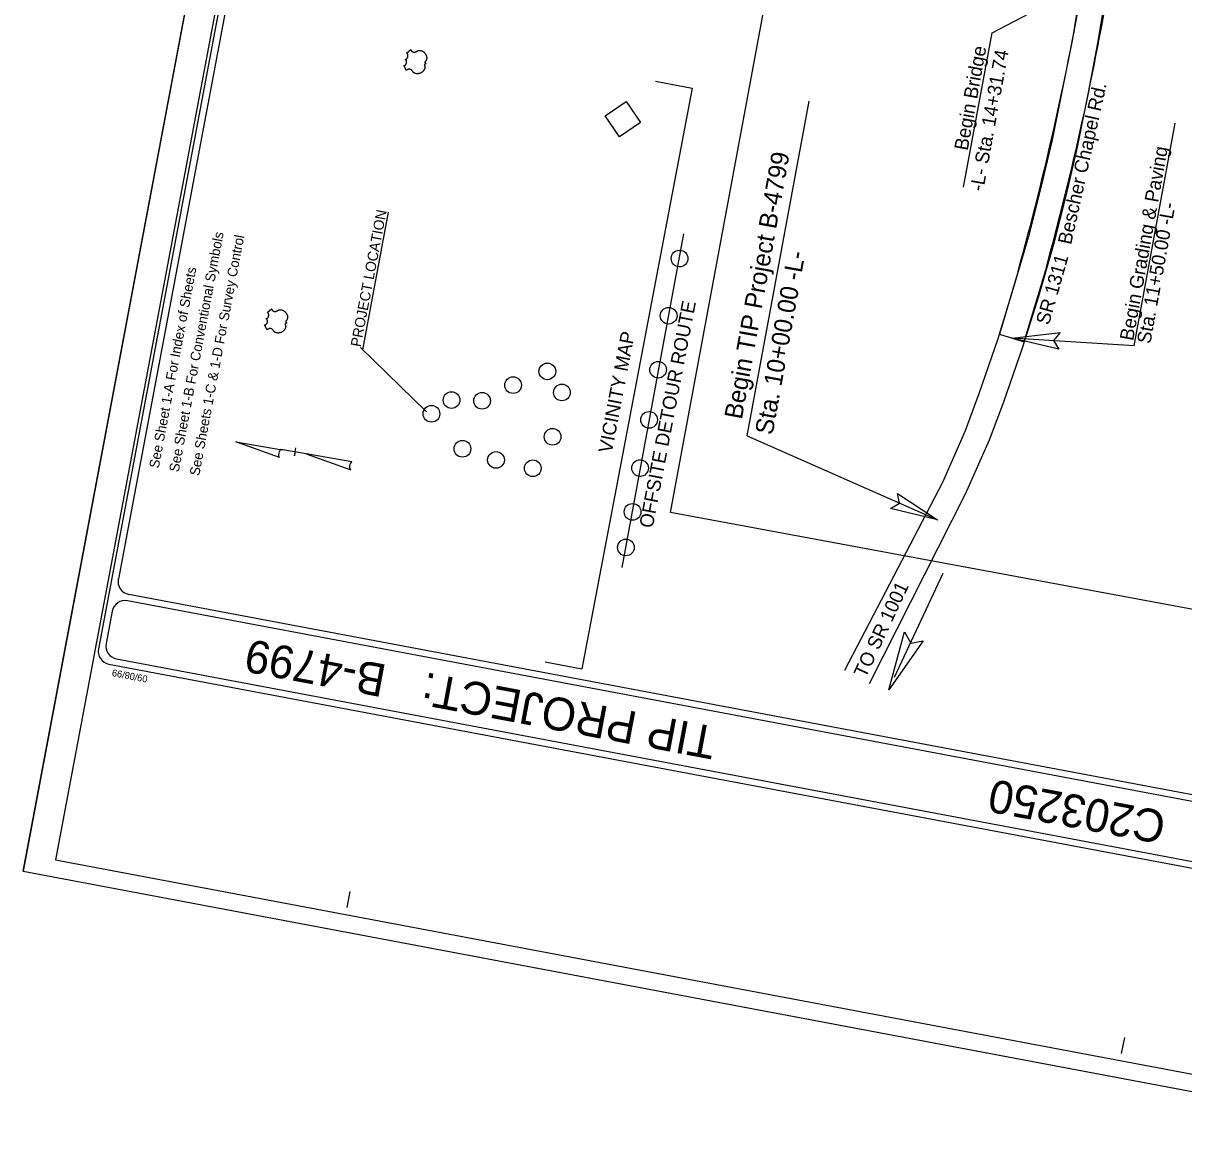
# Model space of a CAD drawing. Extents: x 1665923 to 1668724, y 690926 to 694920.
# Drawn here: x 1665923 to 1666806, y 691127 to 691976 of the extents above; entities that cross this region are included whole.
import ezdxf

# ---------------------------------------------------------------- set-up
doc = ezdxf.new("R2010")
doc.units = 0
for name, color, linetype in [('Default', 7, 'Continuous'), ('Prop Dimension Text', 7, 'Continuous'), ('Prop EOT', 7, 'Continuous'), ('Prop Horizontal Alignment Curve and Spiral Data', 7, 'Continuous'), ('Prop North Arrow for Plan Sheets CELL', 7, 'Continuous'), ('Prop Shade Light', 7, 'Continuous'), ('Prop Terminator CELL', 7, 'Continuous'), ('Sheet Cutting Line CELL', 7, 'Continuous'), ('Sheet Plot Border Inside CELL', 7, 'Continuous'), ('Sheet Plot Border Outside CELL', 7, 'Continuous'), ('Sheet Title CELL', 7, 'Continuous')]:
    doc.layers.add(name, color=color, linetype=linetype)

msp = doc.modelspace()

# ---------------------------------------------------------------- linework, layer by layer
at = {"layer": 'Default'}
for p, q in [((1666415.46, 691603.54), (1666618.88, 692699.33)), ((1666404.03, 691931.75), (1666432.05, 691926.47)), ((1666432.05, 691926.47), (1666348.03, 691484.55)), ((1666181.33, 691727.24), (1666200.8, 691832.11)), ((1666378.61, 691561.73), (1666425.72, 691815.52)), ((1666179.55, 691729.13), (1666229.73, 691680.15)), ((1666816.29, 691529.13), (1666415.46, 691603.54)), ((1666320.02, 691489.84), (1666348.03, 691484.55))]:
    msp.add_line(p, q, dxfattribs=at)
for points in [[(1666732.26, 692049.55), (1666730.91, 692032.26), (1666728.79, 692009.64), (1666721.43, 691963.98), (1666714.02, 691926.14), (1666705.99, 691887.06), (1666697.47, 691850.95), (1666687.93, 691813.6), (1666676.04, 691773.22), (1666664.76, 691735.72), (1666650.35, 691694.65), (1666639.71, 691665.8), (1666622.52, 691626.38), (1666547.97, 691483.33)], [(1666755.68, 692046.05), (1666754.42, 692038.11), (1666751.48, 692027.16), (1666748.07, 692006.66), (1666740.59, 691960.63), (1666733.56, 691923.1), (1666725.06, 691881.58), (1666717.07, 691846.51), (1666706.93, 691807.61), (1666695.59, 691767.97), (1666683.55, 691729.45), (1666669.04, 691687.44), (1666658.04, 691658.5), (1666640.09, 691618.11), (1666566.69, 691473.24)]]:
    msp.add_lwpolyline(points, dxfattribs=at)
for points in [[(1666212.42, 691943.67), (1666212.56, 691943.65), (1666212.73, 691943.65), (1666212.82, 691943.66), (1666213, 691943.7), (1666213.21, 691943.79), (1666213.44, 691943.92), (1666213.64, 691944.09), (1666213.75, 691944.2), (1666213.92, 691944.41), (1666214.08, 691944.64), (1666214.23, 691944.91), (1666214.35, 691945.19), (1666214.45, 691945.5), (1666214.52, 691945.82), (1666214.56, 691946.17), (1666214.57, 691946.56), (1666214.56, 691946.74), (1666214.53, 691946.95), (1666214.5, 691947.15), (1666214.43, 691947.37), (1666214.36, 691947.55), (1666214.3, 691947.69), (1666214.17, 691947.9), (1666214.02, 691948.08), (1666213.93, 691948.16), (1666213.85, 691948.23), (1666213.66, 691948.34), (1666213.58, 691948.38), (1666213.4, 691948.43), (1666213.56, 691948.41), (1666213.65, 691948.4), (1666213.75, 691948.41), (1666213.86, 691948.43), (1666214.02, 691948.47), (1666214.15, 691948.52), (1666214.36, 691948.64), (1666214.46, 691948.71), (1666214.55, 691948.78), (1666214.75, 691948.97), (1666214.94, 691949.21), (1666215.02, 691949.33), (1666215.1, 691949.45), (1666215.18, 691949.61), (1666215.26, 691949.78), (1666215.33, 691949.94), (1666215.39, 691950.12), (1666215.44, 691950.29), (1666215.47, 691950.44), (1666215.51, 691950.62), (1666215.54, 691950.79), (1666215.55, 691950.96), (1666215.56, 691951.16), (1666215.56, 691951.32), (1666215.54, 691951.53), (1666215.52, 691951.72), (1666215.48, 691951.9), (1666215.42, 691952.12), (1666215.35, 691952.31), (1666215.27, 691952.46), (1666215.17, 691952.63), (1666215.04, 691952.8), (1666214.94, 691952.9), (1666214.83, 691952.98), (1666214.72, 691953.06), (1666214.59, 691953.12), (1666214.48, 691953.16), (1666214.38, 691953.19), (1666217.72, 691955.96), (1666217.73, 691955.88), (1666217.78, 691955.68), (1666217.83, 691955.52), (1666217.95, 691955.26), (1666218.02, 691955.14), (1666218.09, 691955.02), (1666218.17, 691954.91), (1666218.24, 691954.81), (1666218.36, 691954.69), (1666218.47, 691954.58), (1666218.6, 691954.46), (1666218.72, 691954.37), (1666218.96, 691954.22), (1666219.12, 691954.13), (1666219.26, 691954.07), (1666219.55, 691953.97), (1666219.69, 691953.93), (1666219.83, 691953.9), (1666219.98, 691953.88), (1666220.12, 691953.86), (1666220.27, 691953.86), (1666220.41, 691953.86), (1666220.58, 691953.86), (1666220.77, 691953.89), (1666220.97, 691953.92), (1666221.29, 691954.01), (1666221.62, 691954.15), (1666221.82, 691954.25), (1666221.99, 691954.36), (1666222.2, 691954.53), (1666222.32, 691954.62), (1666222.48, 691954.72), (1666222.76, 691954.88), (1666222.89, 691954.94), (1666223.04, 691955), (1666223.19, 691955.05), (1666223.34, 691955.1), (1666223.48, 691955.14), (1666223.79, 691955.2), (1666224.08, 691955.22), (1666224.24, 691955.23), (1666224.58, 691955.23), (1666224.74, 691955.22), (1666225.07, 691955.18), (1666225.45, 691955.1), (1666225.81, 691954.99), (1666226.22, 691954.84), (1666226.47, 691954.73), (1666226.74, 691954.58), (1666226.98, 691954.44), (1666227.33, 691954.21), (1666227.58, 691954.02), (1666227.86, 691953.78), (1666228.03, 691953.62), (1666228.21, 691953.43), (1666228.42, 691953.21), (1666228.63, 691952.95), (1666228.85, 691952.65), (1666229.01, 691952.41), (1666229.18, 691952.11), (1666229.28, 691951.92), (1666229.4, 691951.66), (1666229.55, 691951.31), (1666229.66, 691950.98), (1666229.74, 691950.69), (1666229.79, 691950.44), (1666229.84, 691950.13), (1666229.87, 691949.61), (1666229.87, 691949.42), (1666229.86, 691949.2), (1666229.84, 691949), (1666229.81, 691948.81), (1666229.76, 691948.55), (1666229.68, 691948.29), (1666229.6, 691948.06), (1666229.49, 691947.81), (1666229.36, 691947.57), (1666229.22, 691947.34), (1666229.05, 691947.13), (1666228.7, 691946.77), (1666228.61, 691946.66), (1666228.58, 691946.6), (1666228.54, 691946.44), (1666228.54, 691946.29), (1666228.57, 691946.12), (1666228.6, 691946.02), (1666228.66, 691945.88), (1666228.71, 691945.77), (1666228.8, 691945.63), (1666228.87, 691945.54), (1666228.93, 691945.46), (1666229.09, 691945.31), (1666229.16, 691945.25), (1666229.27, 691945.18), (1666229.42, 691945.11), (1666229.21, 691945.1), (1666229.06, 691945.07), (1666228.92, 691945.02), (1666228.8, 691944.97), (1666228.65, 691944.88), (1666228.52, 691944.8), (1666228.4, 691944.69), (1666228.29, 691944.58), (1666228.21, 691944.48), (1666228.15, 691944.39), (1666228.1, 691944.28), (1666228.07, 691944.18), (1666228.06, 691944.1), (1666228.06, 691943.98), (1666228.14, 691943.81), (1666228.2, 691943.65), (1666228.27, 691943.47), (1666228.33, 691943.27), (1666228.36, 691943.12), (1666228.39, 691942.95), (1666228.42, 691942.74), (1666228.43, 691942.53), (1666228.43, 691942.31), (1666228.42, 691942.12), (1666228.39, 691941.92), (1666228.36, 691941.74), (1666228.32, 691941.55), (1666228.27, 691941.38), (1666228.21, 691941.18), (1666228.12, 691940.94), (1666228.03, 691940.74), (1666227.93, 691940.53), (1666227.81, 691940.32), (1666227.67, 691940.1), (1666227.48, 691939.82), (1666227.32, 691939.64), (1666227.06, 691939.34), (1666226.71, 691939.01), (1666226.42, 691938.77), (1666226.18, 691938.59), (1666225.79, 691938.34), (1666225.54, 691938.2), (1666225.1, 691937.99), (1666224.79, 691937.86), (1666224.57, 691937.78), (1666224.21, 691937.67), (1666223.99, 691937.61), (1666223.66, 691937.55), (1666223.38, 691937.5), (1666223.1, 691937.47), (1666222.93, 691937.46), (1666222.63, 691937.46), (1666222.42, 691937.46), (1666222.14, 691937.48), (1666221.84, 691937.52), (1666221.57, 691937.57), (1666221.35, 691937.63), (1666221.09, 691937.71), (1666220.82, 691937.81), (1666220.6, 691937.91), (1666220.44, 691937.99), (1666220.24, 691938.11), (1666220.03, 691938.25), (1666219.84, 691938.4), (1666219.67, 691938.55), (1666219.51, 691938.72), (1666219.37, 691938.88), (1666219.22, 691939.09), (1666219.08, 691939.3), (1666218.99, 691939.49), (1666218.84, 691939.72), (1666218.74, 691939.85), (1666218.61, 691940), (1666218.48, 691940.13), (1666218.37, 691940.23), (1666218.19, 691940.37), (1666218.06, 691940.46), (1666217.85, 691940.59), (1666217.7, 691940.66), (1666217.51, 691940.74), (1666217.32, 691940.8), (1666217.09, 691940.86), (1666216.89, 691940.9), (1666216.65, 691940.92), (1666216.43, 691940.92), (1666216.22, 691940.91), (1666215.98, 691940.87), (1666215.81, 691940.83), (1666215.56, 691940.75), (1666215.33, 691940.65), (1666215.14, 691940.54), (1666214.96, 691940.42), (1666214.82, 691940.3), (1666214.7, 691940.19), (1666214.56, 691940.04), (1666214.44, 691939.89), (1666214.38, 691939.8)], [(1666376.69, 691889.33), (1666365.71, 691905.35), (1666381.74, 691916.33), (1666392.72, 691900.3)], [(1666106.46, 691746.32), (1666106.6, 691746.3), (1666106.77, 691746.3), (1666106.86, 691746.3), (1666107.04, 691746.35), (1666107.26, 691746.43), (1666107.48, 691746.57), (1666107.68, 691746.74), (1666107.8, 691746.85), (1666107.97, 691747.05), (1666108.13, 691747.29), (1666108.27, 691747.56), (1666108.39, 691747.84), (1666108.49, 691748.15), (1666108.56, 691748.47), (1666108.61, 691748.81), (1666108.61, 691749.2), (1666108.6, 691749.39), (1666108.58, 691749.6), (1666108.54, 691749.79), (1666108.47, 691750.01), (1666108.4, 691750.19), (1666108.34, 691750.34), (1666108.21, 691750.55), (1666108.06, 691750.73), (1666107.98, 691750.8), (1666107.89, 691750.87), (1666107.71, 691750.99), (1666107.62, 691751.02), (1666107.44, 691751.08), (1666107.6, 691751.06), (1666107.7, 691751.05), (1666107.8, 691751.06), (1666107.9, 691751.08), (1666108.06, 691751.12), (1666108.19, 691751.17), (1666108.4, 691751.28), (1666108.51, 691751.36), (1666108.59, 691751.43), (1666108.79, 691751.62), (1666108.98, 691751.86), (1666109.07, 691751.98), (1666109.14, 691752.1), (1666109.23, 691752.26), (1666109.3, 691752.42), (1666109.37, 691752.59), (1666109.43, 691752.76), (1666109.48, 691752.94), (1666109.52, 691753.09), (1666109.55, 691753.27), (1666109.58, 691753.44), (1666109.59, 691753.61), (1666109.6, 691753.81), (1666109.6, 691753.96), (1666109.59, 691754.18), (1666109.56, 691754.37), (1666109.52, 691754.54), (1666109.46, 691754.77), (1666109.39, 691754.96), (1666109.32, 691755.1), (1666109.21, 691755.28), (1666109.08, 691755.45), (1666108.98, 691755.55), (1666108.87, 691755.63), (1666108.76, 691755.71), (1666108.63, 691755.77), (1666108.52, 691755.81), (1666108.42, 691755.83), (1666111.76, 691758.61), (1666111.77, 691758.53), (1666111.82, 691758.33), (1666111.88, 691758.17), (1666111.99, 691757.9), (1666112.06, 691757.79), (1666112.13, 691757.67), (1666112.21, 691757.56), (1666112.29, 691757.46), (1666112.4, 691757.34), (1666112.52, 691757.22), (1666112.65, 691757.11), (1666112.76, 691757.02), (1666113.01, 691756.86), (1666113.17, 691756.78), (1666113.3, 691756.72), (1666113.59, 691756.62), (1666113.73, 691756.58), (1666113.87, 691756.55), (1666114.02, 691756.53), (1666114.16, 691756.51), (1666114.32, 691756.51), (1666114.45, 691756.5), (1666114.62, 691756.51), (1666114.81, 691756.53), (1666115.01, 691756.57), (1666115.33, 691756.66), (1666115.66, 691756.79), (1666115.86, 691756.9), (1666116.03, 691757.01), (1666116.24, 691757.18), (1666116.36, 691757.27), (1666116.52, 691757.37), (1666116.8, 691757.53), (1666116.93, 691757.59), (1666117.08, 691757.65), (1666117.23, 691757.7), (1666117.38, 691757.75), (1666117.52, 691757.79), (1666117.83, 691757.84), (1666118.13, 691757.87), (1666118.28, 691757.88), (1666118.62, 691757.87), (1666118.78, 691757.86), (1666119.11, 691757.82), (1666119.49, 691757.75), (1666119.85, 691757.64), (1666120.26, 691757.48), (1666120.51, 691757.37), (1666120.79, 691757.23), (1666121.03, 691757.09), (1666121.37, 691756.86), (1666121.62, 691756.67), (1666121.91, 691756.42), (1666122.08, 691756.26), (1666122.26, 691756.08), (1666122.46, 691755.86), (1666122.67, 691755.6), (1666122.89, 691755.3), (1666123.05, 691755.06), (1666123.23, 691754.75), (1666123.32, 691754.57), (1666123.45, 691754.31), (1666123.59, 691753.96), (1666123.7, 691753.62), (1666123.78, 691753.34), (1666123.83, 691753.09), (1666123.88, 691752.77), (1666123.91, 691752.25), (1666123.91, 691752.07), (1666123.9, 691751.85), (1666123.88, 691751.65), (1666123.85, 691751.45), (1666123.8, 691751.19), (1666123.73, 691750.94), (1666123.64, 691750.7), (1666123.53, 691750.46), (1666123.4, 691750.21), (1666123.26, 691749.99), (1666123.09, 691749.77), (1666122.74, 691749.41), (1666122.66, 691749.31), (1666122.62, 691749.25), (1666122.58, 691749.09), (1666122.58, 691748.93), (1666122.61, 691748.77), (1666122.64, 691748.66), (1666122.7, 691748.53), (1666122.75, 691748.42), (1666122.84, 691748.28), (1666122.91, 691748.18), (1666122.97, 691748.11), (1666123.13, 691747.95), (1666123.21, 691747.89), (1666123.31, 691747.83), (1666123.47, 691747.76), (1666123.25, 691747.75), (1666123.1, 691747.71), (1666122.97, 691747.67), (1666122.85, 691747.62), (1666122.69, 691747.53), (1666122.57, 691747.44), (1666122.44, 691747.34), (1666122.33, 691747.22), (1666122.25, 691747.13), (1666122.2, 691747.04), (1666122.14, 691746.92), (1666122.11, 691746.83), (1666122.1, 691746.75), (1666122.1, 691746.63), (1666122.18, 691746.46), (1666122.25, 691746.29), (1666122.31, 691746.12), (1666122.37, 691745.91), (1666122.41, 691745.77), (1666122.44, 691745.59), (1666122.46, 691745.39), (1666122.47, 691745.18), (1666122.47, 691744.96), (1666122.46, 691744.77), (1666122.44, 691744.56), (1666122.4, 691744.38), (1666122.36, 691744.2), (1666122.31, 691744.03), (1666122.25, 691743.83), (1666122.17, 691743.58), (1666122.08, 691743.39), (1666121.97, 691743.18), (1666121.85, 691742.97), (1666121.71, 691742.74), (1666121.52, 691742.47), (1666121.37, 691742.28), (1666121.11, 691741.99), (1666120.76, 691741.66), (1666120.46, 691741.41), (1666120.22, 691741.24), (1666119.83, 691740.99), (1666119.58, 691740.85), (1666119.15, 691740.63), (1666118.83, 691740.5), (1666118.61, 691740.42), (1666118.25, 691740.31), (1666118.03, 691740.26), (1666117.71, 691740.19), (1666117.42, 691740.15), (1666117.14, 691740.12), (1666116.97, 691740.11), (1666116.67, 691740.11), (1666116.46, 691740.11), (1666116.18, 691740.13), (1666115.88, 691740.17), (1666115.61, 691740.22), (1666115.39, 691740.27), (1666115.13, 691740.35), (1666114.87, 691740.45), (1666114.64, 691740.56), (1666114.48, 691740.64), (1666114.29, 691740.75), (1666114.07, 691740.9), (1666113.88, 691741.05), (1666113.72, 691741.19), (1666113.55, 691741.37), (1666113.41, 691741.53), (1666113.26, 691741.74), (1666113.13, 691741.95), (1666113.03, 691742.14), (1666112.88, 691742.37), (1666112.79, 691742.49), (1666112.65, 691742.65), (1666112.52, 691742.77), (1666112.41, 691742.88), (1666112.23, 691743.02), (1666112.1, 691743.11), (1666111.89, 691743.23), (1666111.74, 691743.3), (1666111.55, 691743.39), (1666111.36, 691743.45), (1666111.13, 691743.51), (1666110.93, 691743.54), (1666110.7, 691743.57), (1666110.47, 691743.57), (1666110.26, 691743.56), (1666110.03, 691743.52), (1666109.85, 691743.48), (1666109.61, 691743.39), (1666109.37, 691743.29), (1666109.18, 691743.18), (1666109, 691743.07), (1666108.86, 691742.95), (1666108.74, 691742.83), (1666108.6, 691742.68), (1666108.49, 691742.54), (1666108.42, 691742.44)]]:
    msp.add_lwpolyline(points, close=True, dxfattribs=at)
for centre in [(1666422.34, 691796.83), (1666414.06, 691753.3), (1666406.01, 691712.21), (1666321.69, 691710.95), (1666295.6, 691700.45), (1666332.8, 691694.9), (1666248.73, 691689.13), (1666271.99, 691688.54), (1666233.47, 691678.67), (1666399.12, 691674.04), (1666325.71, 691661.13), (1666257.09, 691652.02), (1666282.61, 691643.52), (1666310.62, 691637.17), (1666392.3, 691637.33), (1666386.54, 691603.99), (1666381.52, 691576.94)]:
    msp.add_circle(centre, 6.35, dxfattribs=at)
at = {"layer": 'Prop Dimension Text'}
for p, q in [((1666660.41, 691968.66), (1666740.2, 692010.47)), ((1666638.58, 691851.06), (1666660.41, 691968.66)), ((1666585.93, 691478.08), (1666623.09, 691557.27))]:
    msp.add_line(p, q, dxfattribs=at)
at = {"layer": 'Prop EOT'}
msp.add_line((1666665.86, 691739.36), (1666684.79, 691733.41), dxfattribs=at)
at = {"layer": 'Prop Horizontal Alignment Curve and Spiral Data'}
for p, q in [((1666473.81, 691661.81), (1666521.12, 691916.68)), ((1666768.38, 691730.47), (1666799.8, 691899.74)), ((1666768.38, 691730.47), (1666675.63, 691736.29)), ((1666473.81, 691661.81), (1666618.78, 691597.86))]:
    msp.add_line(p, q, dxfattribs=at)
at = {"layer": 'Prop North Arrow for Plan Sheets CELL'}
for p, q in [((1666084.51, 691657.43), (1666084.5, 691657.4)), ((1666084.51, 691657.43), (1666084.5, 691657.4)), ((1666117.7, 691645.41), (1666084.5, 691657.4)), ((1666084.51, 691657.43), (1666119.83, 691651.32)), ((1666138.16, 691648.14), (1666118.8, 691651.5)), ((1666119.83, 691651.32), (1666118.83, 691651.49)), ((1666129.53, 691649.3), (1666129.07, 691646.67)), ((1666129.08, 691646.71), (1666130.1, 691652.62)), ((1666138.16, 691648.14), (1666172.01, 691635.93)), ((1666172.93, 691642.16), (1666138.16, 691648.14)), ((1666129.07, 691646.67), (1666129.07, 691646.64))]:
    msp.add_line(p, q, dxfattribs=at)
for centre, start_param, end_param in [((1666118.6, 691648.4), 0.216388, 2.908219), ((1666172.67, 691639.04), 0.201328, 3.141593)]:
    msp.add_ellipse(centre, major_axis=(0.56, 3.12), ratio=0.461098, start_param=start_param, end_param=end_param, dxfattribs=at)
at = {"layer": 'Prop Shade Light'}
for p, q in [((1666680.11, 691787.3), (1666665.86, 691739.36)), ((1666684.79, 691733.41), (1666699.16, 691781.27)), ((1666665.86, 691739.36), (1666684.79, 691733.41))]:
    msp.add_line(p, q, dxfattribs=at)
for centre, radius, start, end in [((1664481.09, 692397.24), 2282.04, 344.49766, 350.27786), ((1664473.21, 692398.72), 2310, 344.49666, 350.26654)]:
    msp.add_arc(centre, radius, start, end, dxfattribs=at)
at = {"layer": 'Prop Terminator CELL'}
for points in [[(1666711.17, 691727.85), (1666675.63, 691736.29), (1666712.16, 691740.41), (1666707.17, 691734.31)], [(1666588.34, 691618.07), (1666618.78, 691597.86), (1666583.08, 691606.62), (1666589.87, 691610.62)], [(1666607.82, 691505.88), (1666581.69, 691468.44), (1666593.66, 691512.8), (1666598.46, 691504.2)]]:
    msp.add_lwpolyline(points, close=True, dxfattribs=at)
at = {"layer": 'Sheet Cutting Line CELL'}
for q in [(1666234.34, 692985.37), (1667003.64, 691126.87)]:
    msp.add_line((1665922.65, 691330.47), q, dxfattribs=at)
at = {"layer": 'Sheet Plot Border Inside CELL'}
msp.add_lwpolyline([(1666983.99, 691143.8), (1667292.44, 692781.51), (1666255.57, 692976.79), (1665947.12, 691339.09)], close=True, dxfattribs=at)
at = {"layer": 'Sheet Plot Border Outside CELL'}
msp.add_lwpolyline([(1666234.34, 692985.37), (1665922.65, 691330.47), (1667003.64, 691126.87), (1667315.32, 692781.78)], close=True, dxfattribs=at)
at = {"layer": 'Sheet Title CELL'}
for p, q in [((1667004.49, 691347.53), (1666002.12, 691536.32)), ((1666823.61, 691386.68), (1666003.04, 691541.23)), ((1666169.3, 691302.84), (1666171.62, 691315.12)), ((1666169.3, 691302.84), (1666171.62, 691315.12)), ((1666758.94, 691191.79), (1666761.24, 691204.07)), ((1666758.94, 691191.79), (1666761.24, 691204.07))]:
    msp.add_line(p, q, dxfattribs=at)
for points in [[(1666253.91, 692954.22), (1665979.97, 691499.77)], [(1666257.9, 692948.37), (1665995.08, 691552.92)], [(1665990.45, 691528.34), (1665985.81, 691503.77)], [(1665993.79, 691492.11), (1666996.16, 691303.31)], [(1665987.95, 691488.11), (1667000.15, 691297.47)], [(1665987.95, 691488.11), (1667000.15, 691297.47)]]:
    msp.add_lwpolyline(points, dxfattribs=at)
for centre, start, end in [((1666004.85, 691551.07), 169.33381, 259.33381), ((1666000.22, 691526.5), 79.33381, 169.33381), ((1665989.75, 691497.95), 169.33381, 259.33381), ((1665995.59, 691501.93), 169.33381, 259.33381)]:
    msp.add_arc(centre, 10, start, end, dxfattribs=at)

# ---------------------------------------------------------------- texts
at = {"layer": 'Prop Dimension Text'}
for s, height, rotation, p in [('Begin Bridge', 10.5, 79.7152, (1666641.7, 691878.56)), ('-L- Sta. 14+31.74', 10.5, 79.7152, (1666653.54, 691847.56)), ('Bescher Chapel Rd.', 10.5, 77.49709, (1666720.45, 691806.88)), ('PROJECT LOCATION', 7.875, 79.14742, (1666179.55, 691729.13)), ('SR 1311', 10.5, 74.07175, (1666703.56, 691745.69)), ('OFFSITE DETOUR ROUTE', 10.5, 79.14742, (1666401.84, 691591.14)), ('VICINITY MAP', 10.5, 79.14742, (1666370.77, 691648.25)), ('TO SR 1001', 10.5, 64.94065, (1666564.07, 691477.03))]:
    msp.add_text(s, height=height, rotation=rotation, dxfattribs=at).set_placement(p)
at = {"layer": 'Prop Horizontal Alignment Curve and Spiral Data'}
for s, height, p in [('Begin TIP Project B-4799', 13.65, (1666469.78, 691673.92)), ('Begin Grading & Paving', 10.5, (1666767.7, 691733.77)), ('Sta. 11+50.00 -L-', 10.5, (1666780.8, 691731.41)), ('Sta. 10+00.00 -L-', 13.65, (1666493.15, 691662.06))]:
    msp.add_text(s, height=height, rotation=79.79927, dxfattribs=at).set_placement(p)
at = {"layer": 'Sheet Title CELL'}
for s, height, rotation, p in [('See Sheet 1-B For Conventional Symbols', 7.5, 79.33381, (1666041.03, 691633.94)), ('See Sheets 1-C & 1-D For Survey Control', 7.5, 79.33381, (1666056.61, 691631.05)), ('See Sheet 1-A For Index of Sheets', 7.5, 79.33381, (1666025.83, 691636.76)), ('B-4799  ', 25, 169.33381, (1666200.43, 691487.38)), ('09/08/99', 5.25, 169.33381, (1666017.69, 691479.2)), ('TIP PROJECT:', 25, 169.33381, (1666451.58, 691440.08)), ('C203250', 25, 169.33381, (1666793.86, 691375.61))]:
    msp.add_text(s, height=height, rotation=rotation, dxfattribs=at).set_placement(p)

doc.saveas('drawing.dxf')
